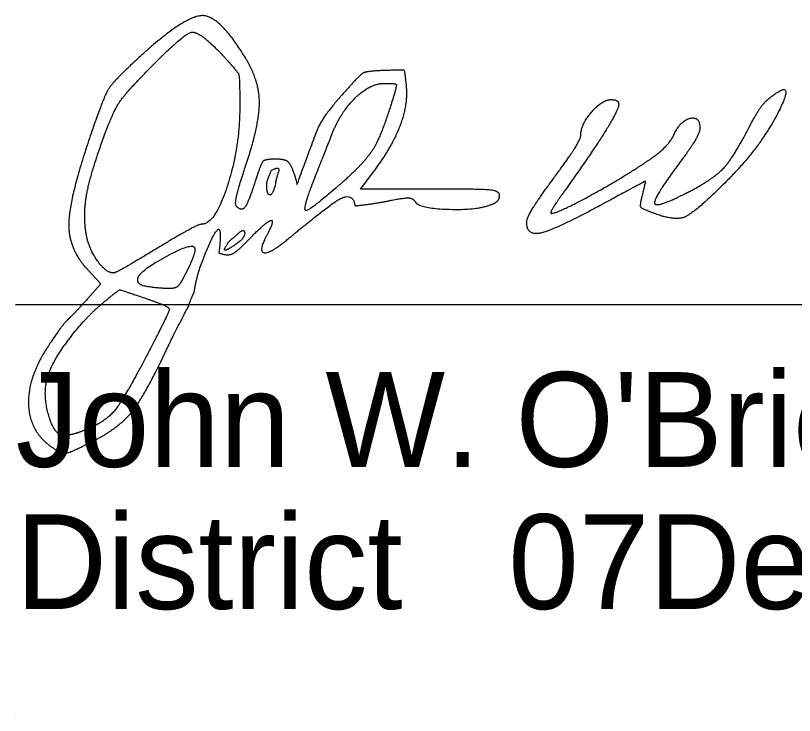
# Model space of a CAD drawing. Extents: x -5.9 to 34, y 0 to 22.
# Drawn here: x 24.528 to 25.679, y 8.319 to 9.353 of the extents above; entities that cross this region are included whole.
import ezdxf

# ---------------------------------------------------------------- set-up
doc = ezdxf.new("R2010")
doc.units = 0
doc.layers.add('SH_Data', color=7, linetype='Continuous')
doc.layers.add('SH_Text', color=7, linetype='Continuous')

msp = doc.modelspace()

# ---------------------------------------------------------------- linework, layer by layer
at = {"layer": 'SH_Data'}
for p, q in [((24.5279, 8.9262), (28.0279, 8.9262)), ((24.5279, 8.3191), (24.5279, 8.3191))]:
    msp.add_line(p, q, dxfattribs=at)
at = {"layer": 'SH_Text'}
for points in [[(25.1404, 9.0966), (25.0375, 9.0966), (25.0558, 9.1206)], [(24.6346, 8.9772), (24.654, 8.9566), (24.6346, 8.9348)]]:
    msp.add_lwpolyline(points, dxfattribs=at)
for points in [[(24.8676, 9.2902), (24.8304, 9.3511), (24.781, 9.3542), (24.7199, 9.2995)], [(24.7219, 9.2706), (24.7758, 9.3259), (24.8, 9.3304), (24.836, 9.2918)], [(24.7199, 9.2995), (24.6737, 9.2582), (24.656, 9.2292), (24.6319, 9.1557)], [(24.836, 9.2918), (24.8564, 9.2699), (24.8592, 9.261), (24.8592, 9.2177)], [(24.8663, 9.1257), (24.888, 9.1897), (24.8885, 9.2559), (24.8676, 9.2902)], [(24.6595, 9.1766), (24.672, 9.2107), (24.69, 9.2379), (24.7219, 9.2706)], [(25.0723, 9.2716), (25.0465, 9.2708), (25.0363, 9.2649), (25.0106, 9.2359)], [(25.1056, 9.2482), (25.1034, 9.271), (25.1012, 9.2725), (25.0723, 9.2716)], [(24.9955, 9.1777), (25.008, 9.2099), (25.052, 9.2526), (25.0726, 9.2526)], [(25.0558, 9.1206), (25.0834, 9.1568), (25.1083, 9.2207), (25.1056, 9.2482)], [(25.0726, 9.2526), (25.0893, 9.2526), (25.0915, 9.2499), (25.0869, 9.2346)], [(25.64, 9.2292), (25.6828, 9.2648), (25.629, 9.1584), (25.5787, 9.1082)], [(25.0106, 9.2359), (24.9936, 9.2167), (24.976, 9.1911), (24.9715, 9.1788)], [(25.0869, 9.2346), (25.0699, 9.1788), (25.0454, 9.1369), (25.013, 9.1083)], [(25.4192, 9.2214), (25.4192, 9.2136), (25.3786, 9.1487), (25.3398, 9.0946)], [(25.3632, 9.1766), (25.3632, 9.1916), (25.3949, 9.2286), (25.4078, 9.2286)], [(25.4078, 9.2286), (25.4141, 9.2286), (25.4192, 9.2254), (25.4192, 9.2214)], [(25.611, 9.1861), (25.6205, 9.2045), (25.6335, 9.2239), (25.64, 9.2292)], [(24.8592, 9.2177), (24.8592, 9.1578), (24.8225, 9.0446), (24.803, 9.0446)], [(25.5007, 9.1766), (25.5102, 9.1974), (25.5392, 9.2045), (25.5392, 9.1861)], [(25.5392, 9.1861), (25.5392, 9.1802), (25.5248, 9.1562), (25.5072, 9.1325)], [(25.5203, 9.0912), (25.5584, 9.1108), (25.5884, 9.1422), (25.611, 9.1861)], [(24.6328, 9.0272), (24.6272, 9.0565), (24.6384, 9.1192), (24.6595, 9.1766)], [(24.9715, 9.1788), (24.9427, 9.1013), (24.9449, 9.105), (24.9381, 9.1235)], [(24.9722, 9.1186), (24.9814, 9.1417), (24.9919, 9.1683), (24.9955, 9.1777)], [(25.3232, 9.1126), (25.3452, 9.1424), (25.3632, 9.1712), (25.3632, 9.1766)], [(25.4494, 9.1297), (25.4726, 9.1445), (25.4957, 9.1656), (25.5007, 9.1766)], [(24.6319, 9.1557), (24.6059, 9.0764), (24.607, 9.0067), (24.6346, 8.9772)], [(24.9121, 9.1406), (24.8965, 9.1406), (24.8905, 9.1345), (24.8829, 9.1106)], [(24.9381, 9.1235), (24.934, 9.1346), (24.9249, 9.1406), (24.9121, 9.1406)], [(24.9062, 9.1246), (24.9197, 9.1312), (24.913, 9.1121), (24.9118, 9.1043)], [(25.3196, 9.0606), (25.3278, 9.0606), (25.4081, 9.1033), (25.4494, 9.1297)], [(25.5072, 9.1325), (25.47, 9.0827), (25.4747, 9.0678), (25.5203, 9.0912)], [(24.8545, 9.0707), (24.8517, 9.0735), (24.8571, 9.0982), (24.8663, 9.1257)], [(24.8992, 9.1001), (24.8992, 9.1043), (24.8998, 9.1099), (24.9062, 9.1246)], [(25.013, 9.1083), (24.962, 9.0635), (24.9513, 9.0662), (24.9722, 9.1186)], [(24.8829, 9.1106), (24.8723, 9.0773), (24.8621, 9.0631), (24.8545, 9.0707)], [(24.9118, 9.1043), (24.9078, 9.087), (24.8992, 9.0886), (24.8992, 9.1001)], [(25.2832, 9.0475), (25.2832, 9.0535), (25.3012, 9.0828), (25.3232, 9.1126)], [(25.4546, 9.0889), (25.4595, 9.1084), (25.4579, 9.108), (25.3928, 9.0728)], [(25.5787, 9.1082), (25.5329, 9.0624), (25.5023, 9.0488), (25.4719, 9.0604)], [(25.2432, 9.0875), (25.2432, 9.0938), (25.2122, 9.0966), (25.1404, 9.0966)], [(25.3398, 9.0946), (25.3264, 9.0759), (25.3173, 9.0606), (25.3196, 9.0606)], [(24.9324, 9.0243), (24.9663, 9.0529), (25.0264, 9.0971), (25.0295, 9.0718)], [(25.0843, 9.0801), (25.1028, 9.0839), (25.1154, 9.0829), (25.1188, 9.0773)], [(25.2306, 9.0735), (25.2375, 9.0761), (25.2432, 9.0824), (25.2432, 9.0875)], [(25.4719, 9.0604), (25.4533, 9.0674), (25.4504, 9.0722), (25.4546, 9.0889)], [(25.0295, 9.0718), (25.0437, 9.0731), (25.0683, 9.0769), (25.0843, 9.0801)], [(25.1188, 9.0773), (25.1245, 9.0681), (25.209, 9.0652), (25.2306, 9.0735)], [(25.3928, 9.0728), (25.3258, 9.0365), (25.2832, 9.0267), (25.2832, 9.0475)], [(24.8708, 9.0202), (24.8973, 9.0478), (24.9119, 9.0524), (24.8995, 9.0291)], [(24.803, 9.0446), (24.7991, 9.0446), (24.7691, 9.0284), (24.7365, 9.0086)], [(24.792, 8.9444), (24.7951, 8.9734), (24.8361, 9.0628), (24.8283, 9.0021)], [(24.8544, 9.0286), (24.8647, 9.0389), (24.8678, 9.028), (24.8603, 9.02)], [(24.6725, 8.9726), (24.6619, 8.9726), (24.6366, 9.0074), (24.6328, 9.0272)], [(24.841, 9.0157), (24.8436, 9.0195), (24.8482, 9.0235), (24.8544, 9.0286)], [(24.8995, 9.0291), (24.886, 9.0038), (24.9047, 9.0011), (24.9324, 9.0243)], [(24.8283, 9.0021), (24.8419, 8.9972), (24.8569, 9.0056), (24.8708, 9.0202)], [(24.8603, 9.02), (24.8459, 9.0093), (24.833, 9.0039), (24.841, 9.0157)], [(24.7365, 9.0086), (24.7039, 8.9888), (24.6751, 8.9726), (24.6725, 8.9726)], [(24.709, 8.9658), (24.7125, 8.9763), (24.786, 9.0165), (24.7916, 9.0109)], [(24.7916, 9.0109), (24.794, 9.0085), (24.7897, 8.9935), (24.7821, 8.9776)], [(24.7821, 8.9776), (24.7724, 8.9573), (24.7633, 8.9489), (24.7518, 8.9495)], [(24.7518, 8.9495), (24.7233, 8.9511), (24.7062, 8.9576), (24.709, 8.9658)], [(24.6594, 8.9304), (24.6806, 8.9477), (24.6826, 8.9479), (24.7183, 8.9357)], [(24.7792, 8.9159), (24.7828, 8.921), (24.7859, 8.9315), (24.792, 8.9444)], [(24.6346, 8.9348), (24.624, 8.9229), (24.6112, 8.9094), (24.6063, 8.9048)], [(24.7183, 8.9357), (24.7386, 8.9288), (24.7552, 8.9213), (24.7552, 8.9191)], [(24.5745, 8.8165), (24.5802, 8.8392), (24.631, 8.9073), (24.6594, 8.9304)], [(24.7552, 8.9191), (24.7552, 8.9169), (24.7405, 8.8868), (24.7226, 8.8522)], [(24.7491, 8.8553), (24.7618, 8.8822), (24.7762, 8.909), (24.7792, 8.9159)], [(24.6063, 8.9048), (24.6013, 8.9003), (24.5878, 8.8823), (24.5763, 8.8648)], [(24.5763, 8.8648), (24.5453, 8.8179), (24.5487, 8.7373), (24.5824, 8.7147)], [(24.7226, 8.8522), (24.688, 8.7858), (24.6592, 8.7513), (24.6287, 8.7397)], [(24.6426, 8.7243), (24.6803, 8.7435), (24.7185, 8.7905), (24.7491, 8.8553)], [(24.599, 8.7326), (24.5855, 8.7326), (24.5682, 8.7916), (24.5745, 8.8165)], [(24.6287, 8.7397), (24.6185, 8.7358), (24.6052, 8.7326), (24.599, 8.7326)], [(24.5824, 8.7147), (24.5964, 8.7054), (24.6097, 8.7075), (24.6426, 8.7243)]]:
    msp.add_open_spline(points, degree=2, dxfattribs=at)

# ---------------------------------------------------------------- texts
for s, p in [("John W. O'Brien", (24.5279, 8.6862)), ('District       Deputy Director', (24.5279, 8.4762)), ('              07', (24.5279, 8.4762))]:
    msp.add_text(s, height=0.14, dxfattribs=at).set_placement(p)

doc.saveas('drawing.dxf')
